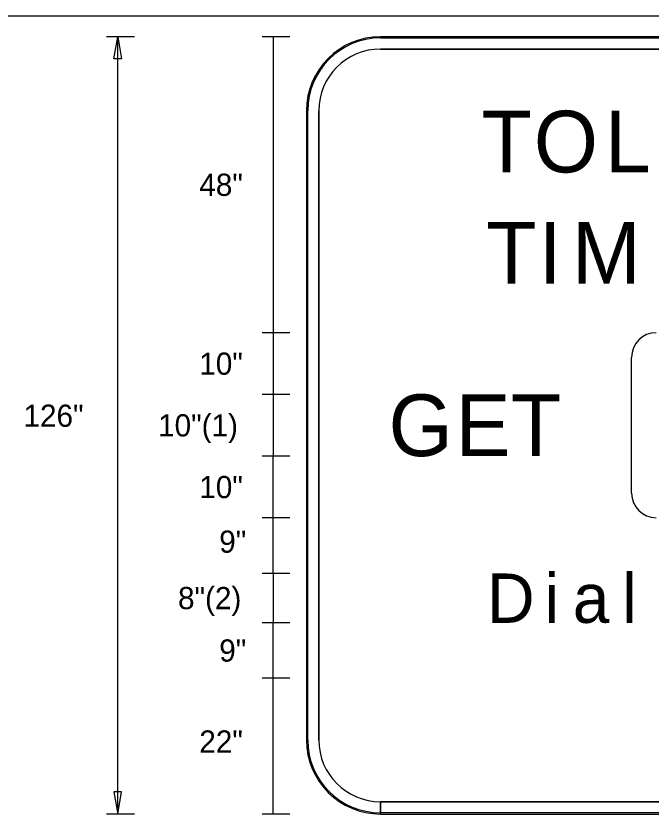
# Model space of a CAD drawing. Extents: x 10268312 to 10268471, y 2141099 to 2141204.
# Drawn here: x 10268380.92 to 10268402.37, y 2141131.78 to 2141158.73 of the extents above; entities that cross this region are included whole.
import ezdxf

# ---------------------------------------------------------------- set-up
doc = ezdxf.new("R2010")
doc.units = 0
for name, color, linetype in [('GSBWFill', 7, 'Continuous'), ('GSColorFill', 7, 'Continuous'), ('GSDims', 7, 'Continuous'), ('GSOutline', 7, 'Continuous'), ('SumBoxLines_dp', 7, 'Continuous')]:
    doc.layers.add(name, color=color, linetype=linetype)

msp = doc.modelspace()

# ---------------------------------------------------------------- linework, layer by layer
at = {"layer": 'GSBWFill'}
for p, q in [((10268419.48, 2141158.028), (10268393.23, 2141158.028)), ((10268393.23, 2141157.612), (10268419.48, 2141157.612)), ((10268390.73, 2141155.528), (10268390.73, 2141134.278)), ((10268391.147, 2141134.278), (10268391.147, 2141155.528)), ((10268401.707, 2141142.615), (10268401.707, 2141147.199)), ((10268393.23, 2141131.778), (10268393.23, 2141132.195)), ((10268419.48, 2141132.195), (10268393.234, 2141132.195)), ((10268393.234, 2141132.195), (10268393.234, 2141131.778)), ((10268393.234, 2141131.778), (10268419.48, 2141131.778))]:
    msp.add_line(p, q, dxfattribs=at)
for centre, radius, start, end in [((10268393.23, 2141155.528), 2.5, 90, 180), ((10268393.23, 2141155.528), 2.083, 90, 180), ((10268402.54, 2141147.199), 0.833, 90, 180), ((10268402.54, 2141142.615), 0.833, 180, 270), ((10268393.23, 2141134.278), 2.5, 180, 270), ((10268393.23, 2141134.278), 2.083, 180, 270)]:
    msp.add_arc(centre, radius, start, end, dxfattribs=at)
at = {"layer": 'GSColorFill'}
for p, q in [((10268419.48, 2141158.028), (10268393.23, 2141158.028)), ((10268419.48, 2141158.028), (10268393.23, 2141158.028)), ((10268419.48, 2141158.028), (10268393.23, 2141158.028)), ((10268393.23, 2141157.987), (10268419.48, 2141157.987)), ((10268393.23, 2141157.612), (10268419.48, 2141157.612)), ((10268390.73, 2141155.528), (10268390.73, 2141134.278)), ((10268390.73, 2141155.528), (10268390.73, 2141134.278)), ((10268390.73, 2141155.528), (10268390.73, 2141134.278)), ((10268390.772, 2141134.278), (10268390.772, 2141155.528)), ((10268391.147, 2141134.278), (10268391.147, 2141155.528)), ((10268393.23, 2141131.778), (10268393.23, 2141132.195)), ((10268419.48, 2141132.195), (10268393.234, 2141132.195)), ((10268393.234, 2141132.195), (10268393.234, 2141131.778)), ((10268393.23, 2141131.778), (10268393.23, 2141131.82)), ((10268393.23, 2141131.778), (10268419.48, 2141131.778)), ((10268419.48, 2141131.82), (10268393.231, 2141131.82)), ((10268393.231, 2141131.82), (10268393.231, 2141131.778)), ((10268393.231, 2141131.778), (10268419.48, 2141131.778)), ((10268393.234, 2141131.778), (10268419.48, 2141131.778))]:
    msp.add_line(p, q, dxfattribs=at)
for centre, radius, start, end in [((10268393.23, 2141155.528), 2.5, 90, 180), ((10268393.23, 2141155.528), 2.5, 90, 180), ((10268393.23, 2141155.528), 2.5, 90, 180), ((10268393.23, 2141155.528), 2.458, 90, 180), ((10268393.23, 2141155.528), 2.083, 90, 180), ((10268393.23, 2141134.278), 2.5, 180, 270), ((10268393.23, 2141134.278), 2.5, 180, 270), ((10268393.23, 2141134.278), 2.5, 180, 270), ((10268393.23, 2141134.278), 2.458, 180, 270), ((10268393.23, 2141134.278), 2.083, 180, 270)]:
    msp.add_arc(centre, radius, start, end, dxfattribs=at)
at = {"layer": 'GSDims'}
for p, q in [((10268384.918, 2141158.028), (10268383.98, 2141158.028)), ((10268384.355, 2141131.778), (10268384.355, 2141158.028)), ((10268390.168, 2141158.028), (10268389.23, 2141158.028)), ((10268389.605, 2141158.028), (10268389.605, 2141148.028)), ((10268390.168, 2141148.028), (10268389.23, 2141148.028)), ((10268389.605, 2141148.028), (10268389.605, 2141145.945)), ((10268390.168, 2141145.945), (10268389.23, 2141145.945)), ((10268389.605, 2141145.945), (10268389.605, 2141143.862)), ((10268390.168, 2141143.862), (10268389.23, 2141143.862)), ((10268389.605, 2141139.903), (10268389.605, 2141143.862)), ((10268390.168, 2141141.778), (10268389.23, 2141141.778)), ((10268390.168, 2141139.904), (10268389.23, 2141139.904)), ((10268390.168, 2141139.904), (10268389.23, 2141139.904)), ((10268389.605, 2141139.904), (10268389.605, 2141138.237)), ((10268390.168, 2141138.237), (10268389.23, 2141138.237)), ((10268390.168, 2141138.237), (10268389.23, 2141138.237)), ((10268389.605, 2141136.362), (10268389.605, 2141138.237)), ((10268390.168, 2141136.362), (10268389.23, 2141136.362)), ((10268389.605, 2141131.778), (10268389.605, 2141136.362)), ((10268384.918, 2141131.778), (10268383.98, 2141131.778)), ((10268390.168, 2141131.778), (10268389.23, 2141131.778))]:
    msp.add_line(p, q, dxfattribs=at)
for points in [[(10268384.355, 2141158.028), (10268384.48, 2141157.278), (10268384.23, 2141157.278)], [(10268384.355, 2141131.778), (10268384.48, 2141132.528), (10268384.23, 2141132.528)]]:
    msp.add_lwpolyline(points, close=True, dxfattribs=at)
at = {"layer": 'GSOutline'}
for p, q in [((10268419.48, 2141158.028), (10268393.23, 2141158.028)), ((10268419.48, 2141157.612), (10268393.23, 2141157.612)), ((10268390.73, 2141155.528), (10268390.73, 2141134.278)), ((10268391.147, 2141155.528), (10268391.147, 2141134.278)), ((10268393.23, 2141132.195), (10268419.48, 2141132.195)), ((10268393.23, 2141131.778), (10268419.48, 2141131.778))]:
    msp.add_line(p, q, dxfattribs=at)
for centre, radius, start, end in [((10268393.23, 2141155.528), 2.5, 90, 180), ((10268393.23, 2141155.528), 2.083, 90, 180), ((10268393.23, 2141134.278), 2.5, 180, 270), ((10268393.23, 2141134.278), 2.083, 180, 270)]:
    msp.add_arc(centre, radius, start, end, dxfattribs=at)
at = {"layer": 'SumBoxLines_dp'}
msp.add_line((10268341.73, 2141158.728), (10268470.98, 2141158.728), dxfattribs=at)

# ---------------------------------------------------------------- texts
at = {"layer": 'GSBWFill'}
for s, height, p in [('T', 2.083, (10268396.64, 2141153.445)), ('O', 2.083, (10268398.409, 2141153.445)), ('L', 2.083, (10268400.813, 2141153.445)), ('T', 2.083, (10268396.802, 2141149.693)), ('I', 2.083, (10268398.571, 2141149.693)), ('M', 2.083, (10268399.698, 2141149.693)), ('G', 2.083, (10268393.503, 2141143.865)), ('E', 2.083, (10268395.762, 2141143.865)), ('T', 2.083, (10268397.631, 2141143.865)), ('D', 1.667, (10268396.826, 2141138.234)), ('i', 1.667, (10268398.769, 2141138.234)), ('l', 1.667, (10268401.393, 2141138.234)), ('a', 1.667, (10268399.723, 2141138.234))]:
    msp.add_text(s, height=height, dxfattribs=at).set_placement(p)
at = {"layer": 'GSColorFill'}
for s, height, p in [('T', 2.083, (10268396.64, 2141153.445)), ('O', 2.083, (10268398.409, 2141153.445)), ('L', 2.083, (10268400.813, 2141153.445)), ('T', 2.083, (10268396.802, 2141149.693)), ('I', 2.083, (10268398.571, 2141149.693)), ('M', 2.083, (10268399.698, 2141149.693)), ('G', 2.083, (10268393.503, 2141143.865)), ('E', 2.083, (10268395.762, 2141143.865)), ('T', 2.083, (10268397.631, 2141143.865)), ('D', 1.667, (10268396.826, 2141138.234)), ('i', 1.667, (10268398.769, 2141138.234)), ('l', 1.667, (10268401.393, 2141138.234)), ('a', 1.667, (10268399.723, 2141138.234))]:
    msp.add_text(s, height=height, dxfattribs=at).set_placement(p)
at = {"layer": 'GSDims'}
for s, p in [('48"', (10268387.111, 2141152.653)), ('10"', (10268387.111, 2141146.612)), ('126"', (10268381.173, 2141144.854)), ('10"(1)', (10268385.719, 2141144.528)), ('10"', (10268387.111, 2141142.445)), ('9"', (10268387.784, 2141140.603)), ('8"(2)', (10268386.392, 2141138.696)), ('9"', (10268387.784, 2141136.925)), ('22"', (10268387.111, 2141133.852))]:
    msp.add_text(s, height=0.75, dxfattribs=at).set_placement(p)

doc.saveas('drawing.dxf')
